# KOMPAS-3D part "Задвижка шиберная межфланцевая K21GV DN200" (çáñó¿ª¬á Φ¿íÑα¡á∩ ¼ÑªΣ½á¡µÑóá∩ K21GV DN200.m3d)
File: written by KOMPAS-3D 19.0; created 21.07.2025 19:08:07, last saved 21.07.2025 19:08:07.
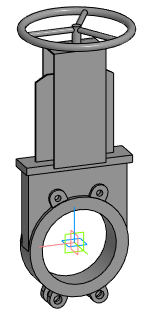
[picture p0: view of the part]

Document properties: Автор: Евгений; Полное имя файла: E:\Dendor Работа Сачек\3D для проектировщиков\2.3 Тип K21GV. Задвижка шиберная межфланцевая\stp_Задвижка шиберная K21GV DN50-400 с маховиком\Задвижка шиберная межфланцевая K21GV DN200.m3d

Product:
- Part/product: Задвижка шиберная межфланцевая K21GV DN200

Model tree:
1. Операция без истории:1  (labels: Задвижка шиберная межфланцевая K21GV DN200)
